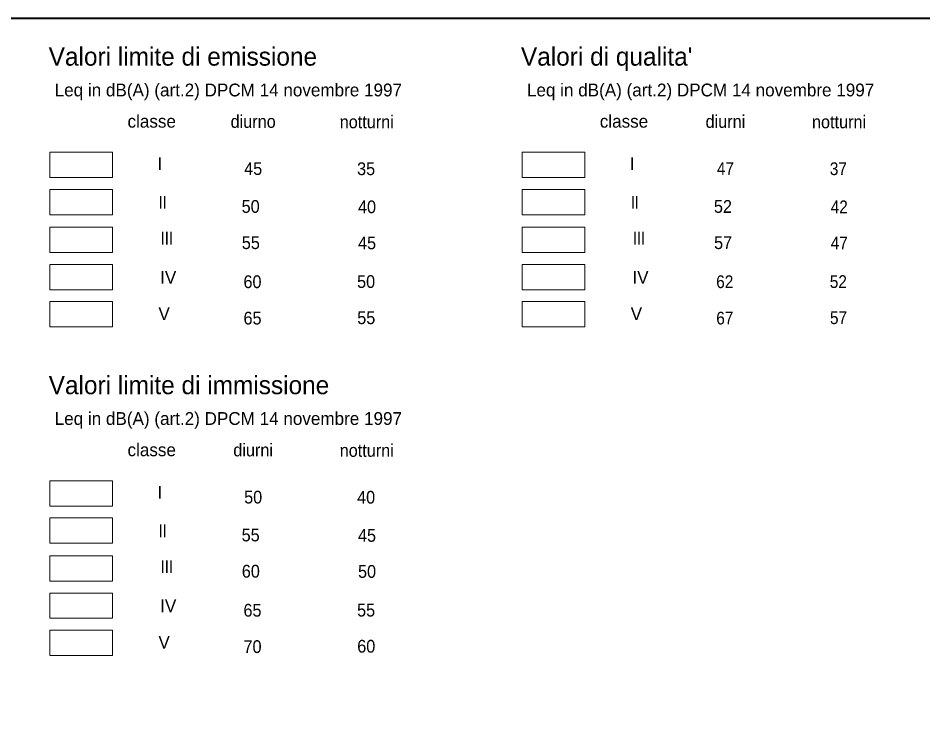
# Model space of a CAD drawing. Extents: x 650468 to 655025, y 889970 to 891591.
# Drawn here: x 652602 to 653594, y 890806 to 891591 of the extents above; entities that cross this region are included whole.
import ezdxf
from ezdxf.enums import TextEntityAlignment as Align

# ---------------------------------------------------------------- set-up
doc = ezdxf.new("R2010")
doc.units = 0
doc.header["$LTSCALE"] = 5.6
doc.layers.add('61', color=7, linetype='Continuous', lineweight=35)

msp = doc.modelspace()

# ---------------------------------------------------------------- linework, layer by layer
at = {"layer": '61', "lineweight": 40}
msp.add_lwpolyline([(653618.27, 891591.08), (653618.27, 889969.62), (652568.28, 889969.62), (652568.28, 891591.08)], close=True, dxfattribs=at)
at = {"layer": '61', "lineweight": 13}
for points in [[(652636.85, 891443.92), (652705.39, 891443.92), (652705.39, 891416.2), (652636.85, 891416.2)], [(653154.68, 891443.93), (653223.22, 891443.93), (653223.22, 891416.21), (653154.68, 891416.21)], [(652636.85, 891403.22), (652705.39, 891403.22), (652705.39, 891375.5), (652636.85, 891375.5)], [(653154.68, 891403.23), (653223.22, 891403.23), (653223.22, 891375.51), (653154.68, 891375.51)], [(652636.85, 891361.64), (652705.39, 891361.64), (652705.39, 891333.92), (652636.85, 891333.92)], [(653154.68, 891361.65), (653223.22, 891361.65), (653223.22, 891333.93), (653154.68, 891333.93)], [(652636.85, 891320.92), (652705.39, 891320.92), (652705.39, 891293.2), (652636.85, 891293.2)], [(653154.68, 891320.93), (653223.22, 891320.93), (653223.22, 891293.21), (653154.68, 891293.21)], [(652636.85, 891280.2), (652705.39, 891280.2), (652705.39, 891252.48), (652636.85, 891252.48)], [(653154.68, 891280.21), (653223.22, 891280.21), (653223.22, 891252.49), (653154.68, 891252.49)], [(652636.85, 891083.66), (652705.39, 891083.66), (652705.39, 891055.94), (652636.85, 891055.94)], [(652636.85, 891042.96), (652705.39, 891042.96), (652705.39, 891015.24), (652636.85, 891015.24)], [(652636.85, 891001.38), (652705.39, 891001.38), (652705.39, 890973.66), (652636.85, 890973.66)], [(652636.85, 890960.66), (652705.39, 890960.66), (652705.39, 890932.94), (652636.85, 890932.94)], [(652636.85, 890919.94), (652705.39, 890919.94), (652705.39, 890892.22), (652636.85, 890892.22)]]:
    msp.add_lwpolyline(points, close=True, dxfattribs=at)

# ---------------------------------------------------------------- texts
at = {"layer": '61'}
for s, height, p in [('Valori limite di emissione', 20, (652635.47, 891538.93)), ("Valori di qualita'", 20, (653153.3, 891538.93)), ('Leq in dB(A) (art.2) DPCM 14 novembre 1997', 14, (652642.05, 891505.25)), ('Leq in dB(A) (art.2) DPCM 14 novembre 1997', 14, (653159.88, 891505.25)), ('Valori limite di immissione', 20, (652635.47, 891178.67)), ('Leq in dB(A) (art.2) DPCM 14 novembre 1997', 14, (652642.05, 891144.99))]:
    msp.add_text(s, height=height, dxfattribs=at).set_placement(p)
for s, p in [('classe', (652748.46, 891470.93)), ('classe', (653266.29, 891470.93)), ('I', (652757.48, 891424.4)), ('I', (653275.31, 891424.4)), ('IV', (652766.56, 891299.84)), ('IV', (653284.4, 891299.84)), ('V', (652762.07, 891259.9)), ('V', (653279.9, 891259.9)), ('classe', (652748.46, 891110.67)), ('I', (652757.48, 891064.14)), ('IV', (652766.56, 890939.58)), ('V', (652762.07, 890899.64))]:
    msp.add_text(s, height=14, dxfattribs=at).set_placement(p, align=Align.CENTER)
for s, width, p in [('diurno', 0.95, (652859.69, 891470.73)), ('notturni', 0.95, (652984.24, 891470.29)), ('diurni', 0.95, (653377.51, 891470.73)), ('notturni', 0.95, (653502.07, 891470.29)), ('45', 0.95, (652859.69, 891419.07)), ('35', 0.95, (652983.53, 891418.89)), ('47', 0.9, (653377.51, 891419.07)), ('37', 0.9, (653501.35, 891418.89)), ('II', 0.8, (652760.42, 891382.08)), ('II', 0.8, (653278.25, 891382.08)), (' 50', 0.95, (652854.47, 891377.53)), ('40', 0.95, (652984.51, 891377.09)), (' 52', 0.95, (653372.31, 891377.53)), ('42', 0.9, (653502.33, 891377.09)), ('III', 0.85, (652765.03, 891342.78)), ('III', 0.85, (653282.85, 891342.78)), (' 55', 0.95, (652854.65, 891337.81)), ('45', 0.95, (652984.55, 891337.55)), (' 57', 0.95, (653372.48, 891337.81)), ('47', 0.9, (653502.37, 891337.55)), ('60', 0.95, (652858.93, 891295.01)), ('50', 0.95, (652983.51, 891295.15)), ('62', 0.9, (653376.75, 891295.01)), ('52', 0.9, (653501.33, 891295.15)), ('65', 0.95, (652858.98, 891255.11)), ('55', 0.95, (652983.69, 891255.53)), ('67', 0.9, (653376.81, 891255.11)), ('57', 0.9, (653501.51, 891255.53)), ('diurni', 0.95, (652859.68, 891110.47)), ('notturni', 0.95, (652984.24, 891110.03)), ('50', 0.95, (652859.69, 891058.81)), ('40', 0.95, (652983.53, 891058.63)), ('II', 0.8, (652760.42, 891021.82)), (' 55', 0.95, (652854.47, 891017.27)), ('45', 0.95, (652984.51, 891016.83)), ('III', 0.85, (652765.03, 890982.52)), (' 60', 0.95, (652854.65, 890977.55)), ('50', 0.95, (652984.55, 890977.29)), ('65', 0.95, (652858.93, 890934.75)), ('55', 0.95, (652983.51, 890934.89)), ('70', 0.95, (652858.98, 890894.85)), ('60', 0.95, (652983.69, 890895.27))]:
    msp.add_text(s, height=14, dxfattribs=dict(at, width=width)).set_placement(p, align=Align.CENTER)

doc.saveas('drawing.dxf')
